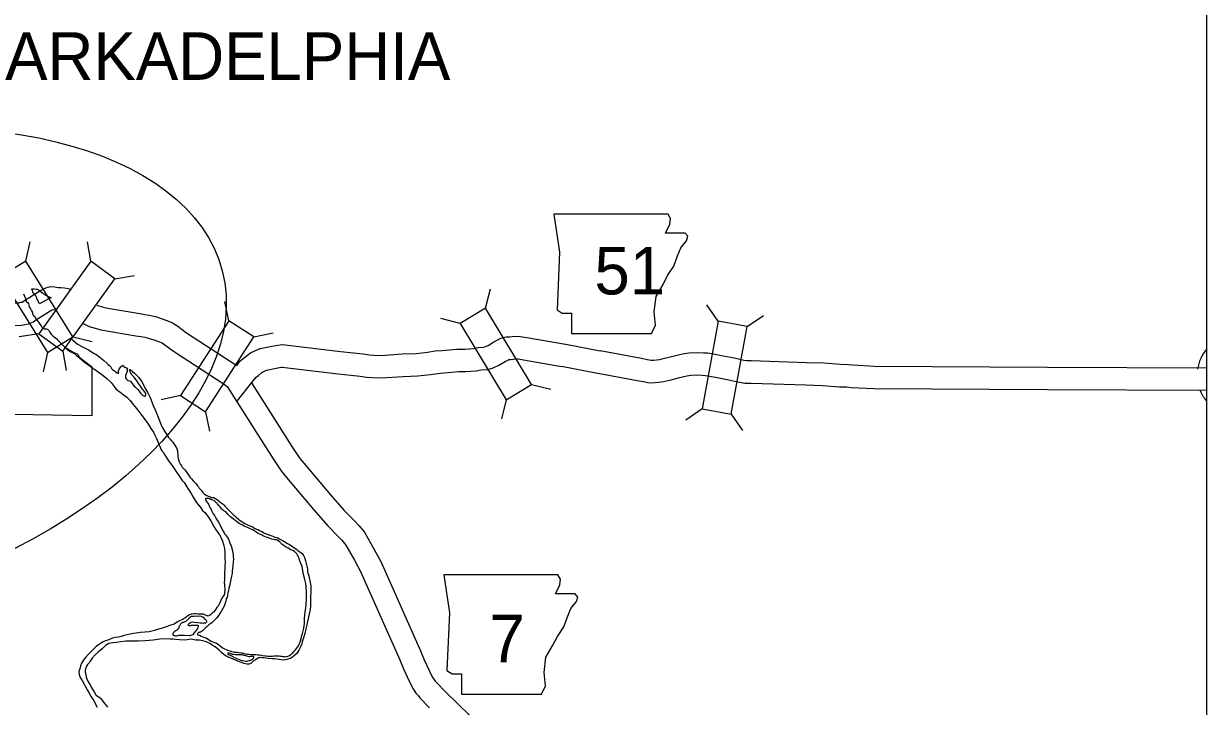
# Model space of a CAD drawing. Extents: x 813775 to 1157140, y 1757555 to 1979907.
# Drawn here: x 864948 to 896470, y 1925573 to 1943761 of the extents above; entities that cross this region are included whole.
import ezdxf

# ---------------------------------------------------------------- set-up
doc = ezdxf.new("R2010")
doc.units = 0
for name, color, linetype in [('Level 10', 7, 'Continuous'), ('Level 20', 7, 'Continuous'), ('Level 21', 7, 'Continuous'), ('Level 24', 7, 'Continuous'), ('Level 6', 7, 'Continuous'), ('Level 9', 7, 'Continuous'), ('R_Draft', 7, 'Continuous')]:
    doc.layers.add(name, color=color, linetype=linetype)

msp = doc.modelspace()

# ---------------------------------------------------------------- linework, layer by layer
at = {"layer": 'Level 10'}
for points in [[(863368, 1936323), (864822, 1936327), (864870, 1936338), (864907, 1936343), (864941, 1936370), (865378, 1936642), (865536, 1936723), (865663, 1936758), (865779, 1936746), (865864, 1936735), (865937, 1936728), (866034, 1936720), (866137, 1936703), (866188, 1936688)], [(863380, 1935723), (864892, 1935727), (864980, 1935747), (865073, 1935761), (865208, 1935817), (865286, 1935878), (865674, 1936119), (865729, 1936147), (865796, 1936139), (865808, 1936138)], [(866897, 1936264), (866912, 1936256), (867017, 1936224), (867134, 1936194), (868042, 1936038), (868174, 1936014), (868294, 1935996), (868463, 1935956), (868641, 1935899), (868762, 1935854), (868912, 1935790), (869054, 1935703), (869287, 1935523), (870626, 1934656)], [(866537, 1935772), (866550, 1935764), (866695, 1935696), (866854, 1935646), (867008, 1935607), (867937, 1935447), (868077, 1935422), (868181, 1935406), (868303, 1935377), (868444, 1935332), (868539, 1935297), (868637, 1935255), (868714, 1935208), (868939, 1935034), (870289, 1934159), (870346, 1934109), (870376, 1934090)], [(870626, 1934656), (870712, 1934766), (870833, 1934863), (870916, 1934927), (870998, 1934992), (871124, 1935056), (871252, 1935103), (871564, 1935171), (871725, 1935199), (871846, 1935214), (872138, 1935176), (873392, 1935027), (873735, 1934993), (873999, 1934963), (874153, 1934940), (874278, 1934932), (874475, 1934924), (875034, 1934961), (875406, 1934977), (875708, 1935008), (875912, 1935041), (876100, 1935056), (876302, 1935072), (876495, 1935090), (876549, 1935093), (876703, 1935090), (876935, 1935111), (877059, 1935130), (877210, 1935144), (877256, 1935156), (877332, 1935191), (877481, 1935281), (877666, 1935381), (877810, 1935418), (877903, 1935417), (878032, 1935431), (878179, 1935425), (878361, 1935402), (879390, 1935222)], [(879396, 1935221), (880315, 1935043)], [(896470, 1934586), (892240, 1934601), (887629, 1934631), (887049, 1934661), (886926, 1934673), (886720, 1934677), (886275, 1934714), (885812, 1934729), (884342, 1934777), (884214, 1934775), (884147, 1934787), (884036, 1934810), (883881, 1934852), (883589, 1934906), (883334, 1934957), (883171, 1934979), (883066, 1934986), (882907, 1934994), (882677, 1934985), (882505, 1934960), (882363, 1934924), (882250, 1934896), (882147, 1934871), (882019, 1934836), (881894, 1934809), (881812, 1934798), (881731, 1934791), (881672, 1934788), (881566, 1934808), (881411, 1934837), (880313, 1935043)], [(870628, 1933694), (871067, 1934247), (871141, 1934340), (871205, 1934391), (871286, 1934455), (871324, 1934485), (871363, 1934505), (871420, 1934525), (871679, 1934582), (871814, 1934605), (871845, 1934609), (872064, 1934581), (873327, 1934430), (873672, 1934397), (873919, 1934369), (874089, 1934343), (874247, 1934333), (874482, 1934323), (875067, 1934361), (875450, 1934378), (875788, 1934413), (875984, 1934445), (876148, 1934457), (876354, 1934475), (876537, 1934491), (876559, 1934492), (876725, 1934490), (877008, 1934515), (877133, 1934534), (877317, 1934551), (877460, 1934590), (877612, 1934659), (877779, 1934760), (877885, 1934817), (877934, 1934817), (878053, 1934830), (878129, 1934827), (878271, 1934809), (879287, 1934631)], [(879282, 1934632), (880201, 1934454)], [(896470, 1933986), (892237, 1934001), (887611, 1934031), (887004, 1934063), (886891, 1934074), (886690, 1934078), (886240, 1934115), (885792, 1934130), (884337, 1934176), (884166, 1934174), (884033, 1934197), (883896, 1934226), (883747, 1934267), (883476, 1934316), (883235, 1934365), (883111, 1934382), (883031, 1934387), (882903, 1934394), (882733, 1934386), (882622, 1934370), (882508, 1934342), (882393, 1934313), (882297, 1934290), (882161, 1934252), (881999, 1934218), (881880, 1934201), (881770, 1934192), (881630, 1934186), (881456, 1934218), (881299, 1934248), (880203, 1934453)], [(870376, 1934090), (871597, 1932169), (871829, 1931824), (871951, 1931672), (872675, 1930817), (873054, 1930384), (873333, 1930100), (873432, 1929996), (873537, 1929868), (873765, 1929463), (873927, 1929168), (874970, 1926812), (875072, 1926569), (875223, 1926244), (875328, 1926035), (875402, 1925922), (875469, 1925850), (875509, 1925804), (875767, 1925534)], [(871022, 1934191), (872100, 1932497), (872313, 1932179), (872414, 1932054), (873130, 1931208), (873494, 1930792), (873764, 1930517), (873881, 1930395), (874034, 1930209), (874290, 1929755), (874465, 1929435), (875521, 1927049), (875621, 1926811), (875763, 1926506), (875848, 1926337), (875877, 1926293), (875918, 1926248), (875954, 1926206), (876193, 1925957), (877817, 1924379)]]:
    msp.add_lwpolyline(points, dxfattribs=at)
at = {"layer": 'Level 20'}
for p, q in [((865004, 1937433), (865124, 1937947)), ((866739, 1937429), (866653, 1937950)), ((865004, 1937433), (864332, 1937015)), ((866259, 1935415), (865004, 1937433)), ((866739, 1937429), (865352, 1935500)), ((867382, 1936967), (866739, 1937429)), ((867382, 1936967), (867903, 1937052)), ((864332, 1937015), (865586, 1934997)), ((865995, 1935038), (867382, 1936967)), ((877261, 1936185), (877388, 1936697)), ((870421, 1935847), (870311, 1936363)), ((883456, 1935833), (883156, 1936267)), ((876583, 1935776), (876070, 1935903)), ((884235, 1935690), (884669, 1935990)), ((865352, 1935500), (864831, 1935415)), ((865352, 1935500), (865995, 1935038)), ((871086, 1935416), (871602, 1935526)), ((865586, 1934997), (866259, 1935415)), ((866259, 1935415), (866773, 1935295)), ((865586, 1934997), (865466, 1934483)), ((865995, 1935038), (866080, 1934517)), ((878488, 1934150), (879001, 1934023)), ((869129, 1933853), (868612, 1933742)), ((877810, 1933741), (877683, 1933229)), ((869793, 1933422), (869904, 1932906)), ((883029, 1933495), (882594, 1933195)), ((883808, 1933353), (884108, 1932919))]:
    msp.add_line(p, q, dxfattribs=at)
for points in [[(878488, 1934150), (877261, 1936185), (876583, 1935776), (877810, 1933741)], [(870421, 1935847), (869129, 1933853), (869793, 1933422), (871086, 1935416)], [(883808, 1933353), (884235, 1935690), (883456, 1935833), (883029, 1933495)]]:
    msp.add_lwpolyline(points, close=True, dxfattribs=at)
at = {"layer": 'Level 21'}
for points in [[(879079, 1938690), (879231, 1937674), (879164, 1936135), (879299, 1936050), (879553, 1936050), (879553, 1935509), (881684, 1935509), (881786, 1935729), (881752, 1936084), (881803, 1936490), (881989, 1936812), (882107, 1937049), (882276, 1937302), (882378, 1937573), (882463, 1937793), (882615, 1937979), (882649, 1938097), (882581, 1938182), (882057, 1938182), (882175, 1938419), (882192, 1938571), (882122, 1938688)], [(876146, 1929078), (876298, 1928063), (876230, 1926524), (876366, 1926439), (876619, 1926439), (876619, 1925898), (878751, 1925898), (878853, 1926118), (878819, 1926473), (878870, 1926879), (879056, 1927201), (879174, 1927437), (879343, 1927691), (879445, 1927962), (879529, 1928182), (879682, 1928368), (879715, 1928486), (879648, 1928571), (879123, 1928571), (879242, 1928808), (879259, 1928960), (879188, 1929077)]]:
    msp.add_lwpolyline(points, close=True, dxfattribs=at)
at = {"layer": 'Level 24'}
for start, end in [(141.1392, 171.6765), (202.1282, 218.8608)]:
    msp.add_arc((897327, 1934399), 1100, start, end, dxfattribs=at)
at = {"layer": 'Level 6'}
msp.add_lwpolyline([(864943, 1936560), (864998, 1936437), (865017, 1936387), (865019, 1936348), (865031, 1936342), (865054, 1936338), (865074, 1936301), (865095, 1936225), (865101, 1936200), (865120, 1936186), (865134, 1936161), (865159, 1936112), (865177, 1936083), (865183, 1936038), (865200, 1935992), (865210, 1935980), (865229, 1935976), (865247, 1935953), (865280, 1935892), (865340, 1935807), (865424, 1935692), (865444, 1935659), (865449, 1935653), (865473, 1935649), (865500, 1935634), (865547, 1935632), (865561, 1935628), (865574, 1935622), (865588, 1935610), (865619, 1935583), (865638, 1935548), (865685, 1935490), (865736, 1935437), (865782, 1935402), (865819, 1935369), (865852, 1935338), (865897, 1935291), (865928, 1935260), (866037, 1935155), (866086, 1935116), (866158, 1935069), (866281, 1935003), (866370, 1934966), (866385, 1934953), (866398, 1934941), (866419, 1934894), (866432, 1934877), (866450, 1934859), (866567, 1934768), (866752, 1934630), (866765, 1934620), (866763, 1933313), (864139, 1933356)], dxfattribs=at)
msp.add_lwpolyline([(865369, 1936293), (865362, 1936319), (865346, 1936352), (865329, 1936391), (865305, 1936406), (865296, 1936455), (865270, 1936511), (865253, 1936535), (865233, 1936550), (865212, 1936573), (865192, 1936616), (865181, 1936649), (865178, 1936661), (865169, 1936691), (865161, 1936700), (865231, 1936695), (865280, 1936691), (865304, 1936686), (865322, 1936680), (865342, 1936672), (865354, 1936663), (865386, 1936634), (865459, 1936579), (865514, 1936543), (865543, 1936526), (865576, 1936511), (865645, 1936477), (865683, 1936460), (865608, 1936426), (865545, 1936396)], close=True, dxfattribs=at)
at = {"layer": 'Level 9'}
for points in [[(866243, 1935339), (866247, 1935335), (866383, 1935225), (866538, 1935146), (866674, 1935073), (866831, 1934974), (866871, 1934958), (866907, 1934932), (866981, 1934875), (867021, 1934843), (867084, 1934789), (867164, 1934716), (867198, 1934684), (867240, 1934650), (867259, 1934624), (867279, 1934593), (867291, 1934573), (867315, 1934547), (867357, 1934517), (867389, 1934495), (867397, 1934489), (867441, 1934459), (867461, 1934450), (867475, 1934452), (867481, 1934458), (867479, 1934472), (867475, 1934496), (867477, 1934516), (867493, 1934556), (867519, 1934596), (867541, 1934614), (867559, 1934634), (867571, 1934644), (867577, 1934652), (867589, 1934658), (867601, 1934656), (867609, 1934650), (867619, 1934626), (867641, 1934608), (867665, 1934604), (867687, 1934596), (867705, 1934584), (867715, 1934567), (867707, 1934550), (867699, 1934546), (867705, 1934503), (867703, 1934493), (867695, 1934469), (867678, 1934429), (867664, 1934389), (867660, 1934353), (867666, 1934323), (867678, 1934297), (867722, 1934255), (867766, 1934243), (867795, 1934235), (867811, 1934214), (867837, 1934174), (867863, 1934142), (867889, 1934106), (867927, 1934076), (867959, 1934048), (867990, 1934017), (868028, 1933971), (868062, 1933919), (868086, 1933891), (868112, 1933867), (868128, 1933856), (868140, 1933846), (868156, 1933838), (868178, 1933836), (868192, 1933848), (868202, 1933872), (868202, 1933898), (868168, 1933964), (868126, 1934011)], [(866069, 1935114), (866132, 1935063), (866184, 1935029), (866238, 1935003), (866302, 1934970), (866351, 1934930), (866401, 1934888), (866439, 1934854), (866497, 1934801), (866570, 1934741), (866632, 1934697), (866710, 1934646), (866778, 1934594), (866891, 1934517), (866951, 1934469), (867027, 1934424), (867166, 1934309), (867276, 1934197), (867357, 1934098), (867405, 1934034), (867455, 1933990), (867510, 1933955), (867602, 1933885), (867694, 1933806), (867783, 1933720), (867861, 1933625), (867920, 1933549), (867992, 1933468), (868099, 1933320), (868213, 1933169), (868276, 1933086), (868342, 1932974), (868409, 1932875), (868447, 1932801), (868492, 1932707), (868526, 1932621), (868550, 1932560), (868566, 1932522), (868597, 1932454), (868617, 1932406), (868637, 1932374), (868663, 1932341), (868705, 1932283), (868738, 1932231), (868812, 1932114), (868875, 1932036), (868939, 1931936), (869000, 1931839), (869082, 1931727), (869122, 1931668), (869175, 1931590), (869223, 1931534), (869269, 1931465), (869320, 1931381), (869376, 1931294), (869422, 1931224), (869465, 1931146), (869519, 1931057), (869559, 1931007), (869590, 1930957), (869672, 1930860), (869700, 1930820), (869718, 1930794), (869773, 1930736), (869871, 1930615), (869950, 1930495), (870019, 1930366), (870059, 1930294), (870127, 1930203)], [(868126, 1934011), (868094, 1934053), (868059, 1934103), (868035, 1934143), (868001, 1934192), (867979, 1934222), (867944, 1934270), (867910, 1934318), (867884, 1934350), (867858, 1934379), (867846, 1934391), (867820, 1934415), (867806, 1934455), (867800, 1934471), (867783, 1934505), (867777, 1934515), (867771, 1934525), (867773, 1934541), (867783, 1934545), (867797, 1934541), (867819, 1934519), (867853, 1934497), (867906, 1934452), (867948, 1934402), (868018, 1934338), (868048, 1934300), (868099, 1934215), (868135, 1934157), (868171, 1934079), (868208, 1934010), (868254, 1933922), (868321, 1933805), (868396, 1933587), (868454, 1933472), (868515, 1933322), (868557, 1933203), (868606, 1933091), (868640, 1933015), (868705, 1932902), (868755, 1932828), (868797, 1932764), (868804, 1932746), (868840, 1932701), (868890, 1932647), (868924, 1932609), (868971, 1932540), (869025, 1932456), (869049, 1932376), (869056, 1932278), (869056, 1932227), (869068, 1932175), (869095, 1932089), (869129, 1932019), (869155, 1931977), (869177, 1931948), (869252, 1931868), (869296, 1931806), (869352, 1931727), (869383, 1931673), (869419, 1931633), (869467, 1931579), (869503, 1931544), (869547, 1931498), (869584, 1931450), (869608, 1931420), (869630, 1931387), (869644, 1931371), (869660, 1931353), (869680, 1931331), (869708, 1931295), (869724, 1931271), (869749, 1931247), (869763, 1931229), (869789, 1931216), (869815, 1931200), (869847, 1931184), (869865, 1931176), (869903, 1931162), (869937, 1931146), (869955, 1931140), (869975, 1931136), (870007, 1931137), (870033, 1931127), (870035, 1931127), (870091, 1931095), (870162, 1931039), (870190, 1931016), (870238, 1930974), (870262, 1930956), (870288, 1930932), (870314, 1930904), (870333, 1930883), (870379, 1930839), (870435, 1930779), (870499, 1930716), (870552, 1930664), (870590, 1930630), (870634, 1930594), (870668, 1930565), (870696, 1930545), (870736, 1930515)], [(872484, 1928616), (872479, 1928762), (872465, 1928848), (872438, 1928951), (872408, 1929083), (872385, 1929185), (872369, 1929300), (872332, 1929382), (872306, 1929454), (872282, 1929528), (872269, 1929561), (872249, 1929599), (872229, 1929633), (872203, 1929667), (872165, 1929695), (872119, 1929722), (872065, 1929746), (871994, 1929786), (871942, 1929816), (871888, 1929847), (871842, 1929885), (871796, 1929927), (871781, 1929947), (871761, 1929964), (871739, 1929976), (871705, 1929996), (871675, 1930006), (871645, 1930008), (871601, 1930014), (871559, 1930027), (871521, 1930043), (871471, 1930061), (871443, 1930069), (871389, 1930089), (871318, 1930122), (871284, 1930138), (871234, 1930162), (871184, 1930188), (871148, 1930209), (871098, 1930251), (871054, 1930279), (871030, 1930287), (870987, 1930306), (870949, 1930324), (870913, 1930336), (870869, 1930356), (870825, 1930376), (870777, 1930399), (870693, 1930445), (870658, 1930469), (870616, 1930504), (870582, 1930526), (870538, 1930556), (870494, 1930592), (870460, 1930622), (870395, 1930683), (870337, 1930755), (870285, 1930786), (870257, 1930806), (870229, 1930828), (870199, 1930862), (870176, 1930898), (870154, 1930924), (870114, 1930971), (870102, 1930985), (870072, 1931005), (870060, 1931019), (870022, 1931053), (869985, 1931069), (869963, 1931079), (869947, 1931086), (869941, 1931088), (869921, 1931098), (869903, 1931100), (869881, 1931108), (869867, 1931110), (869853, 1931112), (869837, 1931112), (869819, 1931112), (869805, 1931112), (869799, 1931104), (869797, 1931094), (869799, 1931078), (869805, 1931060), (869820, 1931032), (869852, 1930998), (869872, 1930960), (869888, 1930918), (869914, 1930871), (869940, 1930831), (869967, 1930775), (870003, 1930705), (870031, 1930654), (870072, 1930588), (870108, 1930530), (870138, 1930484), (870184, 1930403)], [(870736, 1930515), (870797, 1930469), (870847, 1930440), (870897, 1930416), (870973, 1930386), (871043, 1930353), (871105, 1930323), (871158, 1930297), (871192, 1930281), (871234, 1930256), (871294, 1930228), (871370, 1930190), (871436, 1930157), (871507, 1930131), (871587, 1930103), (871643, 1930084), (871693, 1930070), (871725, 1930058), (871757, 1930040), (871839, 1929999), (871908, 1929955), (871976, 1929912), (872048, 1929872), (872088, 1929848), (872150, 1929806), (872192, 1929775), (872225, 1929751), (872257, 1929727), (872309, 1929693), (872339, 1929668), (872367, 1929642), (872405, 1929596), (872432, 1929538), (872460, 1929448), (872478, 1929375), (872509, 1929237), (872515, 1929155), (872546, 1929048), (872601, 1928784), (872605, 1928732), (872598, 1928619), (872592, 1928499), (872589, 1928395), (872589, 1928327), (872593, 1928241), (872580, 1928149), (872554, 1928025), (872527, 1927913), (872507, 1927802), (872495, 1927742), (872470, 1927636), (872442, 1927510), (872401, 1927374), (872375, 1927290), (872359, 1927242), (872336, 1927180), (872284, 1927068), (872228, 1926984), (872177, 1926940), (872125, 1926889), (872099, 1926871), (872061, 1926847), (872013, 1926835), (871971, 1926823), (871921, 1926813), (871871, 1926804), (871815, 1926810), (871761, 1926820), (871701, 1926834), (871643, 1926837), (871569, 1926839), (871468, 1926845), (871400, 1926856), (871342, 1926864), (871292, 1926866), (871252, 1926870), (871224, 1926869), (871198, 1926861), (871168, 1926841), (871128, 1926815), (871067, 1926773), (871003, 1926717), (870955, 1926695), (870893, 1926696), (870819, 1926710), (870728, 1926747), (870616, 1926795), (870534, 1926830), (870472, 1926854), (870367, 1926900), (870295, 1926947), (870219, 1927009), (870159, 1927070), (870106, 1927118), (870050, 1927158), (869976, 1927205), (869906, 1927247), (869838, 1927279), (869789, 1927296), (869723, 1927322), (869639, 1927334)], [(870127, 1930203), (870166, 1930141), (870210, 1930063), (870248, 1929976), (870275, 1929886), (870305, 1929782), (870310, 1929671), (870312, 1929519), (870315, 1929393), (870313, 1929327), (870309, 1929239), (870302, 1929135), (870300, 1929038), (870299, 1928956), (870295, 1928862), (870299, 1928822), (870303, 1928772), (870312, 1928706), (870302, 1928574), (870288, 1928544), (870233, 1928452), (870181, 1928334), (870130, 1928246), (870094, 1928204), (870048, 1928132), (870012, 1928078), (869984, 1928062), (869950, 1928032), (869942, 1928026), (869926, 1928010), (869901, 1927990), (869885, 1927982), (869867, 1927979), (869847, 1927981), (869833, 1927983), (869780, 1928011), (869738, 1928027), (869714, 1928029), (869676, 1928031), (869590, 1928026), (869534, 1928034), (869490, 1928038), (869438, 1928033), (869410, 1928031), (869368, 1928015), (869328, 1927983), (869282, 1927951), (869226, 1927911), (869188, 1927889), (869147, 1927870), (869099, 1927850), (869051, 1927824), (868963, 1927766), (868843, 1927725), (868749, 1927691), (868613, 1927648), (868515, 1927618), (868431, 1927596), (868289, 1927561), (868181, 1927545), (868063, 1927540), (867945, 1927524), (867877, 1927515), (867789, 1927495), (867707, 1927475), (867629, 1927458), (867545, 1927436), (867479, 1927420), (867391, 1927403), (867319, 1927389), (867253, 1927363), (867219, 1927345), (867193, 1927339), (867126, 1927316), (867064, 1927290), (866992, 1927250), (866940, 1927210), (866882, 1927164), (866814, 1927101), (866735, 1927023), (866663, 1926953), (866595, 1926871), (866575, 1926847), (866549, 1926817), (866525, 1926779), (866492, 1926727), (866466, 1926653), (866442, 1926571), (866430, 1926525), (866421, 1926481), (866429, 1926425), (866453, 1926345), (866506, 1926258), (866645, 1926009), (866685, 1925939), (866748, 1925823), (866814, 1925720), (866905, 1925547)], [(870184, 1930403), (870231, 1930305), (870263, 1930241), (870291, 1930192), (870304, 1930170), (870326, 1930144), (870382, 1930070), (870404, 1930028), (870426, 1929986), (870447, 1929925), (870471, 1929863), (870495, 1929793), (870497, 1929777), (870510, 1929717), (870526, 1929650), (870532, 1929624), (870532, 1929598), (870534, 1929558), (870537, 1929500), (870529, 1929412), (870521, 1929320), (870516, 1929238), (870508, 1929170), (870502, 1929114), (870492, 1929044), (870471, 1928962), (870449, 1928861), (870430, 1928777), (870418, 1928719), (870404, 1928651), (870394, 1928609)], [(870394, 1928609), (870381, 1928519), (870371, 1928483), (870349, 1928433), (870325, 1928347), (870288, 1928239), (870260, 1928177), (870224, 1928117), (870178, 1928047), (870143, 1927993), (870097, 1927927), (870045, 1927874), (870009, 1927840), (869969, 1927808), (869935, 1927782), (869886, 1927748), (869842, 1927704), (869798, 1927666), (869768, 1927642), (869744, 1927614), (869714, 1927583), (869660, 1927547), (869642, 1927547), (869622, 1927543), (869610, 1927537), (869598, 1927529), (869586, 1927515), (869582, 1927505), (869582, 1927495), (869584, 1927481), (869593, 1927475), (869639, 1927465), (869679, 1927446), (869767, 1927410), (869809, 1927394), (869875, 1927357), (869947, 1927307), (869992, 1927289), (870036, 1927275), (870084, 1927256), (870134, 1927228), (870196, 1927176), (870268, 1927127), (870303, 1927107), (870349, 1927089), (870385, 1927071), (870449, 1927050), (870487, 1927036), (870529, 1927024), (870561, 1927020), (870635, 1927015), (870679, 1927009), (870741, 1926999), (870771, 1926995), (870856, 1926974), (870900, 1926966), (870948, 1926960), (870996, 1926958), (871038, 1926954), (871090, 1926953), (871134, 1926953), (871190, 1926949), (871230, 1926943), (871280, 1926936), (871318, 1926928), (871372, 1926918), (871410, 1926916), (871464, 1926912), (871516, 1926909), (871578, 1926911), (871616, 1926915), (871640, 1926917), (871672, 1926919), (871710, 1926916), (871754, 1926916), (871794, 1926914), (871828, 1926908), (871856, 1926904), (871887, 1926898), (871903, 1926896), (871941, 1926897), (871969, 1926903), (872013, 1926921), (872056, 1926947), (872096, 1926977), (872120, 1926997), (872152, 1927033), (872190, 1927077), (872270, 1927184), (872329, 1927316), (872345, 1927378), (872372, 1927493), (872378, 1927517), (872412, 1927657), (872429, 1927781), (872437, 1927883), (872446, 1928017), (872458, 1928139), (872477, 1928279), (872486, 1928434), (872484, 1928616)], [(869496, 1927970), (869470, 1927970), (869446, 1927970), (869428, 1927968), (869414, 1927963), (869380, 1927951), (869376, 1927937), (869350, 1927915), (869333, 1927891), (869327, 1927875), (869289, 1927857), (869283, 1927845), (869269, 1927833), (869247, 1927823), (869209, 1927811), (869189, 1927805), (869161, 1927795), (869143, 1927779), (869129, 1927759), (869119, 1927741), (869107, 1927725), (869089, 1927706), (869087, 1927691), (869085, 1927677), (869083, 1927661), (869077, 1927641), (869071, 1927637), (869052, 1927620), (869040, 1927612), (869020, 1927596), (868998, 1927588), (868978, 1927574), (868970, 1927564), (868966, 1927560), (868948, 1927548), (868940, 1927538), (868934, 1927524), (868926, 1927510), (868924, 1927500), (868926, 1927488), (868928, 1927482), (868932, 1927470), (868948, 1927466), (868990, 1927452), (869012, 1927451), (869034, 1927453), (869054, 1927461), (869084, 1927465), (869128, 1927471), (869186, 1927467), (869238, 1927466)], [(869238, 1927466), (869364, 1927460), (869386, 1927462), (869406, 1927470), (869466, 1927491), (869502, 1927533), (869538, 1927577), (869562, 1927611), (869578, 1927631), (869592, 1927659), (869598, 1927673), (869602, 1927691), (869606, 1927701), (869608, 1927715), (869607, 1927719), (869593, 1927729), (869569, 1927731), (869533, 1927730), (869521, 1927730), (869487, 1927728), (869445, 1927730), (869419, 1927724), (869391, 1927722), (869377, 1927720), (869359, 1927718), (869355, 1927718), (869333, 1927732), (869331, 1927742), (869343, 1927764), (869357, 1927780), (869385, 1927800), (869409, 1927812), (869447, 1927820), (869491, 1927818), (869581, 1927803), (869651, 1927795), (869705, 1927795), (869737, 1927793), (869751, 1927799), (869797, 1927799), (869803, 1927800), (869817, 1927812), (869829, 1927832), (869827, 1927846), (869819, 1927859), (869795, 1927883), (869779, 1927895), (869759, 1927923), (869723, 1927947), (869691, 1927963), (869636, 1927974), (869594, 1927970), (869544, 1927974), (869496, 1927970)], [(869639, 1927334), (869541, 1927337), (869407, 1927359), (869253, 1927340), (869103, 1927347), (868997, 1927355), (868923, 1927362), (868855, 1927364), (868752, 1927368), (868574, 1927363), (868400, 1927340), (868184, 1927321), (867998, 1927312), (867836, 1927312), (867672, 1927309), (867540, 1927294), (867426, 1927274), (867326, 1927265), (867216, 1927251), (867130, 1927191), (867044, 1927108), (866945, 1927022), (866855, 1926944), (866775, 1926856), (866735, 1926800), (866714, 1926772), (866694, 1926728), (866668, 1926701), (866648, 1926685), (866620, 1926643), (866610, 1926621), (866604, 1926597), (866584, 1926539), (866583, 1926487), (866603, 1926418), (866613, 1926362), (866631, 1926310), (866662, 1926244), (866730, 1926125), (866749, 1926085), (866791, 1926013), (866823, 1925957), (866869, 1925876), (866880, 1925872), (866914, 1925848), (866948, 1925830), (866998, 1925787), (867046, 1925723), (867113, 1925641), (867179, 1925552)], [(870868, 1926916), (870826, 1926930), (870812, 1926935), (870792, 1926939), (870772, 1926943), (870732, 1926943), (870692, 1926947), (870675, 1926949), (870633, 1926949), (870593, 1926948), (870543, 1926950), (870513, 1926956), (870499, 1926960), (870487, 1926966), (870471, 1926974), (870451, 1926980), (870433, 1926990), (870399, 1926994), (870391, 1926994), (870387, 1926984), (870389, 1926966), (870403, 1926956), (870433, 1926942), (870469, 1926926), (870520, 1926904), (870550, 1926878), (870592, 1926863), (870608, 1926851), (870648, 1926837), (870696, 1926825), (870734, 1926803), (870762, 1926794), (870816, 1926782), (870872, 1926776), (870908, 1926776)], [(870908, 1926776), (870994, 1926807), (871014, 1926813), (871026, 1926817), (871038, 1926823), (871054, 1926833), (871060, 1926841), (871064, 1926845), (871080, 1926863), (871080, 1926883), (871070, 1926897), (871056, 1926901), (871026, 1926902), (870992, 1926898), (870970, 1926896), (870958, 1926896), (870868, 1926916)]]:
    msp.add_lwpolyline(points, dxfattribs=at)
at = {"layer": 'R_Draft'}
msp.add_lwpolyline([(823472, 1968812), (896470, 1968812), (896470, 1905247), (823472, 1905247)], close=True, dxfattribs=at)
msp.add_lwpolyline([(823472, 1968812), (896470, 1968812), (896470, 1905247), (823472, 1905247)], close=True, dxfattribs=at)
msp.add_ellipse((858856, 1934247), major_axis=(11387, 2926), ratio=0.533954, dxfattribs=at)

# ---------------------------------------------------------------- texts
at = {"layer": 'Level 21'}
for s, height, p in [('51', 1267.2, (880160, 1936547)), ('7', 1267, (877363, 1926746))]:
    msp.add_text(s, height=height, dxfattribs=at).set_placement(p)
at = {"layer": 'Level 6'}
msp.add_text('ARKADELPHIA', height=1267.2, dxfattribs=at).set_placement((864454, 1942264))

doc.saveas('drawing.dxf')
